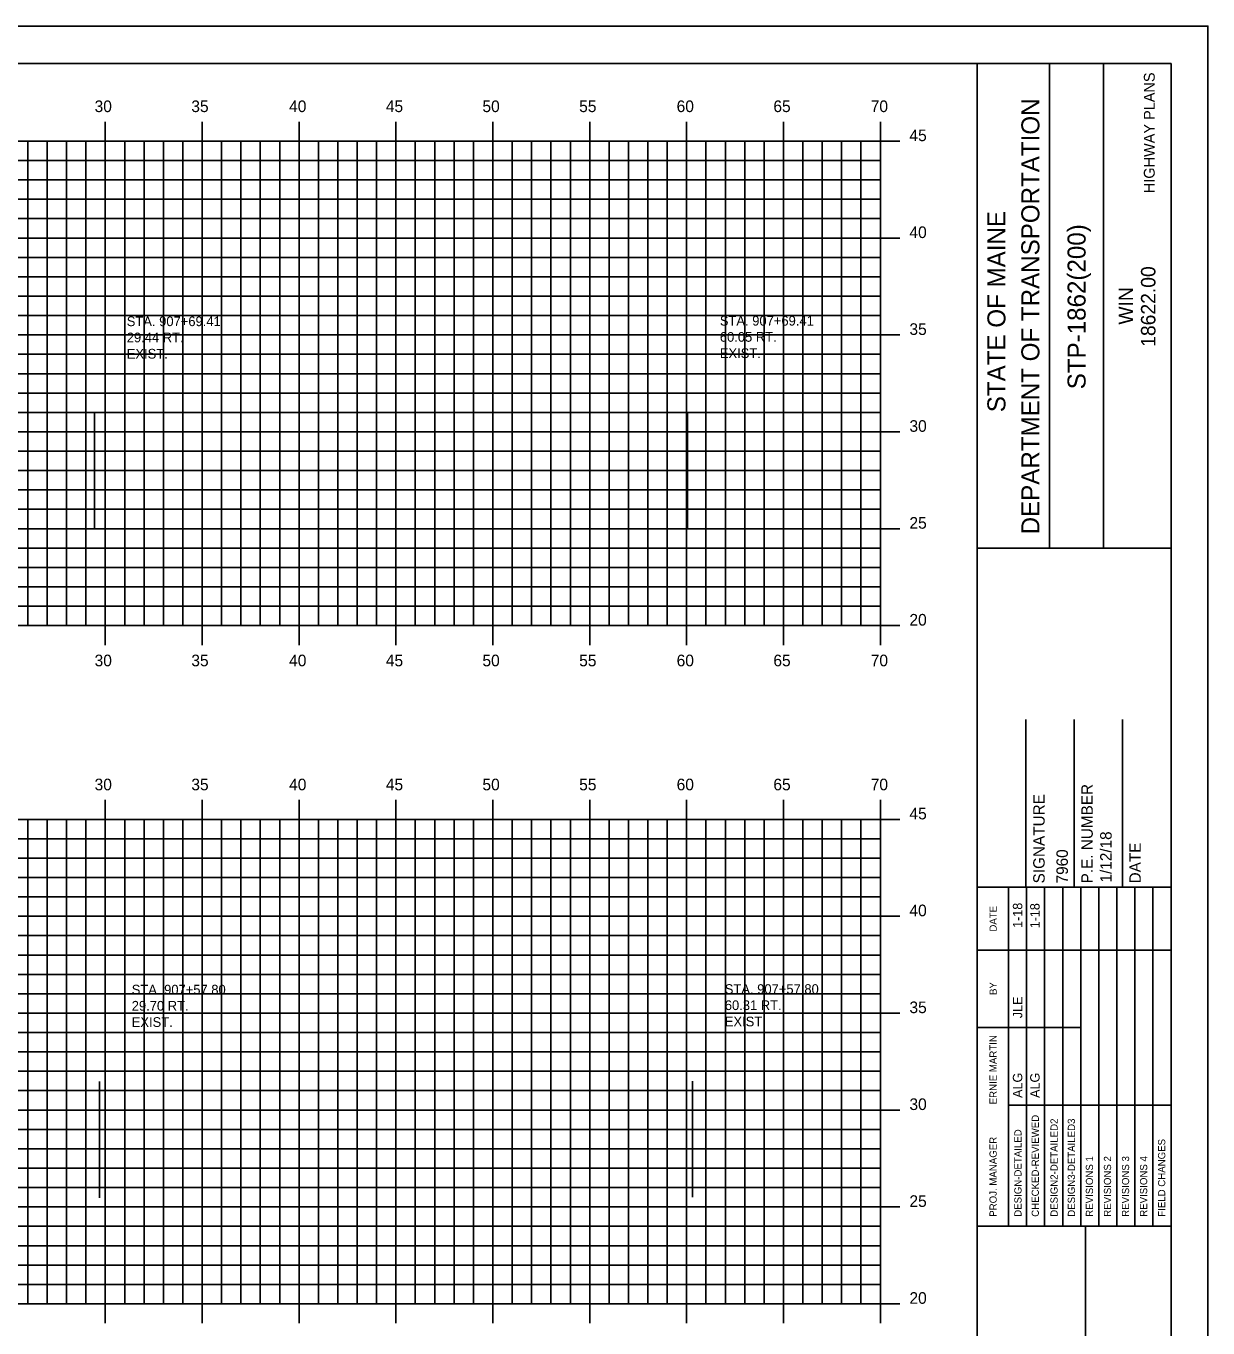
# Model space of a CAD drawing. Extents: x 1025909 to 1026079, y 394697 to 394807.
# Drawn here: x 1026017.6 to 1026078.6, y 394739.4 to 394806.5 of the extents above; entities that cross this region are included whole.
import ezdxf

# ---------------------------------------------------------------- set-up
doc = ezdxf.new("R2010")
doc.units = 0
for name, color, linetype in [('BORDER', 7, 'Continuous'), ('D_Text_Monospaced', 7, 'Continuous'), ('H_V ANNOTATION', 7, 'Continuous'), ('HIGHWAY_TITLE', 7, 'Continuous'), ('MAJOR', 7, 'Continuous'), ('MINOR', 7, 'Continuous'), ('PLOT BOUNDARY', 7, 'Continuous'), ('S_Utilities_UG_Sanitary_Sewer', 7, 'Continuous')]:
    doc.layers.add(name, color=color, linetype=linetype)

msp = doc.modelspace()

# ---------------------------------------------------------------- linework, layer by layer
at = {"layer": 'BORDER'}
for p, q in [((1026076.677, 394804.607), (1025916.677, 394804.607)), ((1026066.677, 394699.607), (1026066.677, 394804.61)), ((1026070.405, 394779.604), (1026070.405, 394804.604)), ((1026073.2, 394779.604), (1026073.2, 394804.604)), ((1026076.677, 394699.607), (1026076.677, 394804.607)), ((1026066.678, 394779.601), (1026076.677, 394779.601)), ((1026069.177, 394762.11), (1026069.177, 394770.757)), ((1026071.677, 394762.11), (1026071.677, 394770.757)), ((1026074.177, 394762.11), (1026074.177, 394770.757)), ((1026066.677, 394762.11), (1026076.677, 394762.11)), ((1026066.677, 394744.61), (1026076.677, 394744.61)), ((1026072.268, 394709.61), (1026072.268, 394744.61))]:
    msp.add_line(p, q, dxfattribs=at)
for points in [[(1026068.292, 394758.86), (1026068.292, 394762.11)], [(1026069.224, 394744.613), (1026069.224, 394762.11)], [(1026070.156, 394762.11), (1026070.156, 394744.613)], [(1026071.088, 394744.613), (1026071.088, 394762.11)], [(1026072.019, 394744.613), (1026072.019, 394762.11)], [(1026072.951, 394744.613), (1026072.951, 394762.11)], [(1026073.883, 394744.613), (1026073.883, 394762.11)], [(1026074.814, 394744.613), (1026074.814, 394762.11)], [(1026075.746, 394744.613), (1026075.746, 394762.11)], [(1026068.293, 394744.613), (1026068.293, 394761.404)], [(1026066.677, 394758.86), (1026076.677, 394758.86)], [(1026066.677, 394754.86), (1026068.293, 394754.86)], [(1026068.292, 394754.86), (1026072.018, 394754.86)], [(1026068.292, 394750.86), (1026076.677, 394750.86)]]:
    msp.add_lwpolyline(points, dxfattribs=at)
at = {"layer": 'MAJOR'}
for p, q in [((1026021.677, 394801.609), (1026021.677, 394800.607)), ((1026026.677, 394801.609), (1026026.677, 394800.607)), ((1026031.677, 394801.609), (1026031.677, 394800.607)), ((1026036.677, 394801.609), (1026036.677, 394800.607)), ((1026041.677, 394801.609), (1026041.677, 394800.607)), ((1026046.677, 394801.609), (1026046.677, 394800.607)), ((1026051.677, 394801.609), (1026051.677, 394800.607)), ((1026056.677, 394801.609), (1026056.677, 394800.607)), ((1026061.677, 394801.609), (1026061.677, 394800.607)), ((1025921.677, 394800.607), (1026061.677, 394800.607)), ((1026021.677, 394775.607), (1026021.677, 394800.607)), ((1026026.677, 394775.607), (1026026.677, 394800.607)), ((1026031.677, 394775.607), (1026031.677, 394800.607)), ((1026036.677, 394775.607), (1026036.677, 394800.607)), ((1026041.677, 394775.607), (1026041.677, 394800.607)), ((1026046.677, 394775.607), (1026046.677, 394800.607)), ((1026051.677, 394775.607), (1026051.677, 394800.607)), ((1026056.677, 394775.607), (1026056.677, 394800.607)), ((1026062.679, 394800.607), (1026060.675, 394800.607)), ((1026061.677, 394775.607), (1026061.677, 394800.607)), ((1025921.677, 394795.607), (1026061.677, 394795.607)), ((1026062.679, 394795.607), (1026060.675, 394795.607)), ((1025921.677, 394790.607), (1026061.677, 394790.607)), ((1026062.679, 394790.607), (1026060.675, 394790.607)), ((1025921.677, 394785.607), (1026061.677, 394785.607)), ((1026062.679, 394785.607), (1026060.675, 394785.607)), ((1025921.677, 394780.607), (1026061.677, 394780.607)), ((1026062.679, 394780.607), (1026060.675, 394780.607)), ((1025921.677, 394775.607), (1026061.677, 394775.607)), ((1026021.677, 394774.605), (1026021.677, 394775.607)), ((1026026.677, 394774.605), (1026026.677, 394775.607)), ((1026031.677, 394774.605), (1026031.677, 394775.607)), ((1026036.677, 394774.605), (1026036.677, 394775.607)), ((1026041.677, 394774.605), (1026041.677, 394775.607)), ((1026046.677, 394774.605), (1026046.677, 394775.607)), ((1026051.677, 394774.605), (1026051.677, 394775.607)), ((1026056.677, 394774.605), (1026056.677, 394775.607)), ((1026062.679, 394775.607), (1026060.675, 394775.607)), ((1026061.677, 394774.605), (1026061.677, 394775.607)), ((1026021.677, 394766.609), (1026021.677, 394765.607)), ((1026026.677, 394766.609), (1026026.677, 394765.607)), ((1026031.677, 394766.609), (1026031.677, 394765.607)), ((1026036.677, 394766.609), (1026036.677, 394765.607)), ((1026041.677, 394766.609), (1026041.677, 394765.607)), ((1026046.677, 394766.609), (1026046.677, 394765.607)), ((1026051.677, 394766.609), (1026051.677, 394765.607)), ((1026056.677, 394766.609), (1026056.677, 394765.607)), ((1026061.677, 394766.609), (1026061.677, 394765.607)), ((1025921.677, 394765.607), (1026061.677, 394765.607)), ((1026021.677, 394740.607), (1026021.677, 394765.607)), ((1026026.677, 394740.607), (1026026.677, 394765.607)), ((1026031.677, 394740.607), (1026031.677, 394765.607)), ((1026036.677, 394740.607), (1026036.677, 394765.607)), ((1026041.677, 394740.607), (1026041.677, 394765.607)), ((1026046.677, 394740.607), (1026046.677, 394765.607)), ((1026051.677, 394740.607), (1026051.677, 394765.607)), ((1026056.677, 394740.607), (1026056.677, 394765.607)), ((1026062.679, 394765.607), (1026060.675, 394765.607)), ((1026061.677, 394740.607), (1026061.677, 394765.607)), ((1025921.677, 394760.607), (1026061.677, 394760.607)), ((1026062.679, 394760.607), (1026060.675, 394760.607)), ((1025921.677, 394755.607), (1026061.677, 394755.607)), ((1026062.679, 394755.607), (1026060.675, 394755.607)), ((1025921.677, 394750.607), (1026061.677, 394750.607)), ((1026062.679, 394750.607), (1026060.675, 394750.607)), ((1025921.677, 394745.607), (1026061.677, 394745.607)), ((1026062.679, 394745.607), (1026060.675, 394745.607)), ((1025921.677, 394740.607), (1026061.677, 394740.607)), ((1026021.677, 394739.605), (1026021.677, 394740.607)), ((1026026.677, 394739.605), (1026026.677, 394740.607)), ((1026031.677, 394739.605), (1026031.677, 394740.607)), ((1026036.677, 394739.605), (1026036.677, 394740.607)), ((1026041.677, 394739.605), (1026041.677, 394740.607)), ((1026046.677, 394739.605), (1026046.677, 394740.607)), ((1026051.677, 394739.605), (1026051.677, 394740.607)), ((1026056.677, 394739.605), (1026056.677, 394740.607)), ((1026062.679, 394740.607), (1026060.675, 394740.607)), ((1026061.677, 394739.605), (1026061.677, 394740.607))]:
    msp.add_line(p, q, dxfattribs=at)
at = {"layer": 'MINOR'}
for p, q in [((1026017.677, 394775.607), (1026017.677, 394800.607)), ((1026018.677, 394775.607), (1026018.677, 394800.607)), ((1026019.677, 394775.607), (1026019.677, 394800.607)), ((1026020.677, 394775.607), (1026020.677, 394800.607)), ((1026022.677, 394775.607), (1026022.677, 394800.607)), ((1026023.677, 394775.607), (1026023.677, 394800.607)), ((1026024.677, 394775.607), (1026024.677, 394800.607)), ((1026025.677, 394775.607), (1026025.677, 394800.607)), ((1026027.677, 394775.607), (1026027.677, 394800.607)), ((1026028.677, 394775.607), (1026028.677, 394800.607)), ((1026029.677, 394775.607), (1026029.677, 394800.607)), ((1026030.677, 394775.607), (1026030.677, 394800.607)), ((1026032.677, 394775.607), (1026032.677, 394800.607)), ((1026033.677, 394775.607), (1026033.677, 394800.607)), ((1026034.677, 394775.607), (1026034.677, 394800.607)), ((1026035.677, 394775.607), (1026035.677, 394800.607)), ((1026037.677, 394775.607), (1026037.677, 394800.607)), ((1026038.677, 394775.607), (1026038.677, 394800.607)), ((1026039.677, 394775.607), (1026039.677, 394800.607)), ((1026040.677, 394775.607), (1026040.677, 394800.607)), ((1026042.677, 394775.607), (1026042.677, 394800.607)), ((1026043.677, 394775.607), (1026043.677, 394800.607)), ((1026044.677, 394775.607), (1026044.677, 394800.607)), ((1026045.677, 394775.607), (1026045.677, 394800.607)), ((1026047.677, 394775.607), (1026047.677, 394800.607)), ((1026048.677, 394775.607), (1026048.677, 394800.607)), ((1026049.677, 394775.607), (1026049.677, 394800.607)), ((1026050.677, 394775.607), (1026050.677, 394800.607)), ((1026052.677, 394775.607), (1026052.677, 394800.607)), ((1026053.677, 394775.607), (1026053.677, 394800.607)), ((1026054.677, 394775.607), (1026054.677, 394800.607)), ((1026055.677, 394775.607), (1026055.677, 394800.607)), ((1026057.677, 394775.607), (1026057.677, 394800.607)), ((1026058.677, 394775.607), (1026058.677, 394800.607)), ((1026059.677, 394775.607), (1026059.677, 394800.607)), ((1026060.677, 394775.607), (1026060.677, 394800.607)), ((1025921.677, 394799.607), (1026061.677, 394799.607)), ((1026061.677, 394799.607), (1026060.675, 394799.607)), ((1025921.677, 394798.607), (1026061.677, 394798.607)), ((1026061.677, 394798.607), (1026060.675, 394798.607)), ((1025921.677, 394797.607), (1026061.677, 394797.607)), ((1026061.677, 394797.607), (1026060.675, 394797.607)), ((1025921.677, 394796.607), (1026061.677, 394796.607)), ((1026061.677, 394796.607), (1026060.675, 394796.607)), ((1025921.677, 394794.607), (1026061.677, 394794.607)), ((1026061.677, 394794.607), (1026060.675, 394794.607)), ((1025921.677, 394793.607), (1026061.677, 394793.607)), ((1026061.677, 394793.607), (1026060.675, 394793.607)), ((1025921.677, 394792.607), (1026061.677, 394792.607)), ((1026061.677, 394792.607), (1026060.675, 394792.607)), ((1025921.677, 394791.607), (1026061.677, 394791.607)), ((1026061.677, 394791.607), (1026060.675, 394791.607)), ((1025921.677, 394789.607), (1026061.677, 394789.607)), ((1026061.677, 394789.607), (1026060.675, 394789.607)), ((1025921.677, 394788.607), (1026061.677, 394788.607)), ((1026061.677, 394788.607), (1026060.675, 394788.607)), ((1025921.677, 394787.607), (1026061.677, 394787.607)), ((1026061.677, 394787.607), (1026060.675, 394787.607)), ((1025921.677, 394786.607), (1026061.677, 394786.607)), ((1026061.677, 394786.607), (1026060.675, 394786.607)), ((1025921.677, 394784.607), (1026061.677, 394784.607)), ((1026061.677, 394784.607), (1026060.675, 394784.607)), ((1025921.677, 394783.607), (1026061.677, 394783.607)), ((1026061.677, 394783.607), (1026060.675, 394783.607)), ((1025921.677, 394782.607), (1026061.677, 394782.607)), ((1026061.677, 394782.607), (1026060.675, 394782.607)), ((1025921.677, 394781.607), (1026061.677, 394781.607)), ((1026061.677, 394781.607), (1026060.675, 394781.607)), ((1025921.677, 394779.607), (1026061.677, 394779.607)), ((1026061.677, 394779.607), (1026060.675, 394779.607)), ((1025921.677, 394778.607), (1026061.677, 394778.607)), ((1026061.677, 394778.607), (1026060.675, 394778.607)), ((1025921.677, 394777.607), (1026061.677, 394777.607)), ((1026061.677, 394777.607), (1026060.675, 394777.607)), ((1025921.677, 394776.607), (1026061.677, 394776.607)), ((1026061.677, 394776.607), (1026060.675, 394776.607)), ((1026017.677, 394740.607), (1026017.677, 394765.607)), ((1026018.677, 394740.607), (1026018.677, 394765.607)), ((1026019.677, 394740.607), (1026019.677, 394765.607)), ((1026020.677, 394740.607), (1026020.677, 394765.607)), ((1026022.677, 394740.607), (1026022.677, 394765.607)), ((1026023.677, 394740.607), (1026023.677, 394765.607)), ((1026024.677, 394740.607), (1026024.677, 394765.607)), ((1026025.677, 394740.607), (1026025.677, 394765.607)), ((1026027.677, 394740.607), (1026027.677, 394765.607)), ((1026028.677, 394740.607), (1026028.677, 394765.607)), ((1026029.677, 394740.607), (1026029.677, 394765.607)), ((1026030.677, 394740.607), (1026030.677, 394765.607)), ((1026032.677, 394740.607), (1026032.677, 394765.607)), ((1026033.677, 394740.607), (1026033.677, 394765.607)), ((1026034.677, 394740.607), (1026034.677, 394765.607)), ((1026035.677, 394740.607), (1026035.677, 394765.607)), ((1026037.677, 394740.607), (1026037.677, 394765.607)), ((1026038.677, 394740.607), (1026038.677, 394765.607)), ((1026039.677, 394740.607), (1026039.677, 394765.607)), ((1026040.677, 394740.607), (1026040.677, 394765.607)), ((1026042.677, 394740.607), (1026042.677, 394765.607)), ((1026043.677, 394740.607), (1026043.677, 394765.607)), ((1026044.677, 394740.607), (1026044.677, 394765.607)), ((1026045.677, 394740.607), (1026045.677, 394765.607)), ((1026047.677, 394740.607), (1026047.677, 394765.607)), ((1026048.677, 394740.607), (1026048.677, 394765.607)), ((1026049.677, 394740.607), (1026049.677, 394765.607)), ((1026050.677, 394740.607), (1026050.677, 394765.607)), ((1026052.677, 394740.607), (1026052.677, 394765.607)), ((1026053.677, 394740.607), (1026053.677, 394765.607)), ((1026054.677, 394740.607), (1026054.677, 394765.607)), ((1026055.677, 394740.607), (1026055.677, 394765.607)), ((1026057.677, 394740.607), (1026057.677, 394765.607)), ((1026058.677, 394740.607), (1026058.677, 394765.607)), ((1026059.677, 394740.607), (1026059.677, 394765.607)), ((1026060.677, 394740.607), (1026060.677, 394765.607)), ((1025921.677, 394764.607), (1026061.677, 394764.607)), ((1026061.677, 394764.607), (1026060.675, 394764.607)), ((1025921.677, 394763.607), (1026061.677, 394763.607)), ((1026061.677, 394763.607), (1026060.675, 394763.607)), ((1025921.677, 394762.607), (1026061.677, 394762.607)), ((1026061.677, 394762.607), (1026060.675, 394762.607)), ((1025921.677, 394761.607), (1026061.677, 394761.607)), ((1026061.677, 394761.607), (1026060.675, 394761.607)), ((1025921.677, 394759.607), (1026061.677, 394759.607)), ((1026061.677, 394759.607), (1026060.675, 394759.607)), ((1025921.677, 394758.607), (1026061.677, 394758.607)), ((1026061.677, 394758.607), (1026060.675, 394758.607)), ((1025921.677, 394757.607), (1026061.677, 394757.607)), ((1026061.677, 394757.607), (1026060.675, 394757.607)), ((1025921.677, 394756.607), (1026061.677, 394756.607)), ((1026061.677, 394756.607), (1026060.675, 394756.607)), ((1025921.677, 394754.607), (1026061.677, 394754.607)), ((1026061.677, 394754.607), (1026060.675, 394754.607)), ((1025921.677, 394753.607), (1026061.677, 394753.607)), ((1026061.677, 394753.607), (1026060.675, 394753.607)), ((1025921.677, 394752.607), (1026061.677, 394752.607)), ((1026061.677, 394752.607), (1026060.675, 394752.607)), ((1025921.677, 394751.607), (1026061.677, 394751.607)), ((1026061.677, 394751.607), (1026060.675, 394751.607)), ((1025921.677, 394749.607), (1026061.677, 394749.607)), ((1026061.677, 394749.607), (1026060.675, 394749.607)), ((1025921.677, 394748.607), (1026061.677, 394748.607)), ((1026061.677, 394748.607), (1026060.675, 394748.607)), ((1025921.677, 394747.607), (1026061.677, 394747.607)), ((1026061.677, 394747.607), (1026060.675, 394747.607)), ((1025921.677, 394746.607), (1026061.677, 394746.607)), ((1026061.677, 394746.607), (1026060.675, 394746.607)), ((1025921.677, 394744.607), (1026061.677, 394744.607)), ((1026061.677, 394744.607), (1026060.675, 394744.607)), ((1025921.677, 394743.607), (1026061.677, 394743.607)), ((1026061.677, 394743.607), (1026060.675, 394743.607)), ((1025921.677, 394742.607), (1026061.677, 394742.607)), ((1026061.677, 394742.607), (1026060.675, 394742.607)), ((1025921.677, 394741.607), (1026061.677, 394741.607)), ((1026061.677, 394741.607), (1026060.675, 394741.607))]:
    msp.add_line(p, q, dxfattribs=at)
at = {"layer": 'PLOT BOUNDARY'}
msp.add_lwpolyline([(1025908.583, 394696.548), (1026078.583, 394696.548), (1026078.583, 394806.548), (1025908.583, 394806.548)], close=True, dxfattribs=at)
at = {"layer": 'S_Utilities_UG_Sanitary_Sewer'}
for p, q in [((1026021.118, 394786.562), (1026021.118, 394780.562)), ((1026051.726, 394786.591), (1026051.726, 394780.591)), ((1026051.982, 394752.102), (1026051.982, 394746.102)), ((1026021.374, 394752.072), (1026021.374, 394746.072))]:
    msp.add_line(p, q, dxfattribs=at)

# ---------------------------------------------------------------- texts
at = {"layer": 'BORDER'}
for s, height, p in [('DEPARTMENT OF TRANSPORTATION', 0.93176, (1026069.884, 394780.313)), ('STATE OF MAINE', 0.93176, (1026068.132, 394786.619)), ('STP-1862(200)', 0.93176, (1026072.269, 394787.801)), ('18622.00', 0.7453, (1026075.872, 394789.993)), ('WIN', 0.7453, (1026074.713, 394791.137)), ('P.E. NUMBER', 0.59055, (1026072.638, 394762.302)), ('SIGNATURE', 0.5906, (1026070.157, 394762.302)), ('1/12/18', 0.5906, (1026073.611, 394762.35)), ('DATE', 0.5906, (1026075.118, 394762.302)), ('7960', 0.5906, (1026071.354, 394762.302)), ('DATE', 0.3714, (1026067.681, 394759.815)), ('1-18', 0.4845, (1026069, 394760.007)), ('1-18', 0.4845, (1026069.894, 394759.985)), ('BY', 0.3714, (1026067.681, 394756.545)), ('JLE', 0.4845, (1026069, 394755.345)), ('ERNIE MARTIN', 0.37275, (1026067.681, 394750.901)), ('ALG', 0.4845, (1026069, 394751.233)), ('ALG', 0.4845, (1026069.894, 394751.233)), ('CHECKED-REVIEWED', 0.37275, (1026069.858, 394745.098)), ('DESIGN2-DETAILED2', 0.37275, (1026070.827, 394745.098)), ('DESIGN3-DETAILED3', 0.37275, (1026071.721, 394745.098)), ('DESIGN-DETAILED', 0.37275, (1026068.963, 394745.098)), ('PROJ. MANAGER', 0.37275, (1026067.681, 394745.098)), ('FIELD CHANGES', 0.37275, (1026076.38, 394745.098)), ('REVISIONS 1', 0.37275, (1026072.653, 394745.098)), ('REVISIONS 2', 0.37275, (1026073.584, 394745.098)), ('REVISIONS 3', 0.37275, (1026074.516, 394745.098)), ('REVISIONS 4', 0.37275, (1026075.448, 394745.098))]:
    msp.add_text(s, height=height, rotation=90, dxfattribs=at).set_placement(p)
at = {"layer": 'D_Text_Monospaced'}
for s, height, p in [('STA. 907+69.41', 0.49998, (1026022.785, 394791.06)), ('STA. 907+69.41', 0.49998, (1026053.392, 394791.089)), ('29.44 RT.', 0.5, (1026022.785, 394790.226)), ('60.05 RT.', 0.5, (1026053.392, 394790.255)), ('EXIST. ', 0.5, (1026022.785, 394789.386)), ('EXIST. ', 0.5, (1026053.392, 394789.415)), ('STA. 907+57.80', 0.49998, (1026023.041, 394756.57)), ('STA. 907+57.80', 0.49998, (1026053.648, 394756.6)), ('29.70 RT.', 0.5, (1026023.041, 394755.736)), ('60.31 RT.', 0.5, (1026053.648, 394755.766)), ('EXIST. ', 0.5, (1026023.041, 394754.896)), ('EXIST. ', 0.5, (1026053.648, 394754.926))]:
    msp.add_text(s, height=height, dxfattribs=at).set_placement(p)
at = {"layer": 'H_V ANNOTATION'}
for s, p in [('30', (1026021.125, 394802.107)), ('35', (1026026.117, 394802.107)), ('40', (1026031.163, 394802.107)), ('45', (1026036.155, 394802.107)), ('50', (1026041.141, 394802.107)), ('55', (1026046.133, 394802.107)), ('60', (1026051.163, 394802.107)), ('65', (1026056.155, 394802.107)), ('70', (1026061.179, 394802.107)), ('45', (1026063.177, 394800.607)), ('40', (1026063.177, 394795.607)), ('35', (1026063.177, 394790.607)), ('30', (1026063.177, 394785.607)), ('25', (1026063.177, 394780.607)), ('20', (1026063.177, 394775.607)), ('30', (1026021.125, 394773.507)), ('35', (1026026.117, 394773.507)), ('40', (1026031.163, 394773.507)), ('45', (1026036.155, 394773.507)), ('50', (1026041.141, 394773.507)), ('55', (1026046.133, 394773.507)), ('60', (1026051.163, 394773.507)), ('65', (1026056.155, 394773.507)), ('70', (1026061.179, 394773.507)), ('30', (1026021.125, 394767.107)), ('35', (1026026.117, 394767.107)), ('40', (1026031.163, 394767.107)), ('45', (1026036.155, 394767.107)), ('50', (1026041.141, 394767.107)), ('55', (1026046.133, 394767.107)), ('60', (1026051.163, 394767.107)), ('65', (1026056.155, 394767.107)), ('70', (1026061.179, 394767.107)), ('45', (1026063.177, 394765.607)), ('40', (1026063.177, 394760.607)), ('35', (1026063.177, 394755.607)), ('30', (1026063.177, 394750.607)), ('25', (1026063.177, 394745.607)), ('20', (1026063.177, 394740.607))]:
    msp.add_text(s, height=0.6, dxfattribs=at).set_placement(p)
at = {"layer": 'HIGHWAY_TITLE'}
msp.add_text('HIGHWAY PLANS', height=0.55901, rotation=90, dxfattribs=at).set_placement((1026075.835, 394797.922))

doc.saveas('drawing.dxf')
